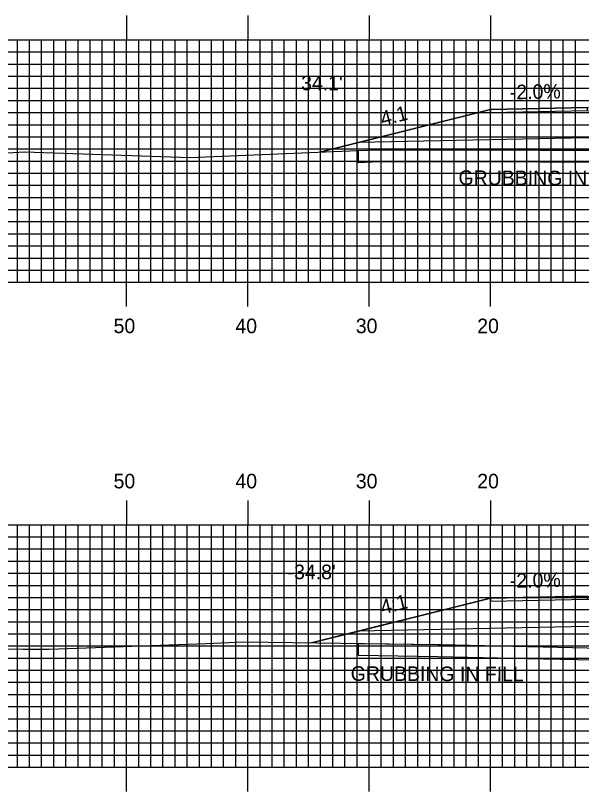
# Model space of a CAD drawing. Extents: x 1814522 to 1814865, y 442591 to 442811.
# Drawn here: x 1814628.4 to 1814675, y 442686.7 to 442750.7 of the extents above; entities that cross this region are included whole.
import ezdxf

# ---------------------------------------------------------------- set-up
doc = ezdxf.new("R2010")
doc.units = 0
for name, color, linetype in [('ANNOTATION', 7, 'Continuous'), ('D_Roadway_Centerline', 7, 'Continuous'), ('D_Roadway_Edge_Shoulder', 7, 'Continuous'), ('D_Roadway_SlopeLines', 7, 'Continuous'), ('D_Roadway_SubGrade', 7, 'Continuous'), ('D_Text_Standard', 7, 'Continuous'), ('GRUBBING IN FILL', 7, 'Continuous'), ('H_V ANNOTATION', 7, 'Continuous'), ('MAJOR', 7, 'Continuous'), ('MINOR', 7, 'Continuous'), ('S_Roadway_Centerline', 7, 'Continuous')]:
    doc.layers.add(name, color=color, linetype=linetype)

msp = doc.modelspace()

# ---------------------------------------------------------------- linework, layer by layer
at = {"layer": 'D_Roadway_Centerline'}
for points in [[(1814653.448, 442739.4), (1814656.638, 442740.197), (1814667.508, 442742.915), (1814675.508, 442743.075), (1814687.508, 442742.499), (1814699.508, 442741.923), (1814707.508, 442741.539), (1814719.884, 442738.445), (1814723.884, 442737.445), (1814725.374, 442738.19), (1814726.624, 442738.721), (1814727.874, 442739.063), (1814729.124, 442739.217), (1814730.374, 442739.183)], [(1814652.747, 442698.927), (1814656.638, 442699.899), (1814667.508, 442702.617), (1814675.508, 442702.777), (1814687.508, 442702.201), (1814699.508, 442701.625), (1814707.508, 442701.241), (1814719.884, 442698.147), (1814723.884, 442697.147), (1814725.557, 442697.984), (1814726.807, 442698.531), (1814728.057, 442698.923), (1814729.307, 442699.16), (1814730.557, 442699.241)]]:
    msp.add_lwpolyline(points, dxfattribs=at)
at = {"layer": 'D_Roadway_Edge_Shoulder'}
for points in [[(1814675.508, 442743.075), (1814667.508, 442742.915), (1814667.508, 442742.665), (1814675.508, 442742.825)], [(1814675.508, 442702.777), (1814667.508, 442702.617), (1814667.508, 442702.367), (1814675.508, 442702.527)]]:
    msp.add_lwpolyline(points, close=True, dxfattribs=at)
at = {"layer": 'D_Roadway_SlopeLines'}
for points in [[(1814667.508, 442742.915), (1814653.448, 442739.4)], [(1814667.508, 442702.617), (1814652.747, 442698.927)]]:
    msp.add_lwpolyline(points, dxfattribs=at)
at = {"layer": 'D_Roadway_SubGrade'}
for points in [[(1814675.508, 442740.575), (1814656.638, 442740.197), (1814667.508, 442742.915), (1814667.508, 442742.665), (1814675.508, 442742.825), (1814687.508, 442742.249), (1814699.508, 442741.673), (1814707.508, 442741.289), (1814707.508, 442741.539), (1814719.884, 442738.445), (1814699.508, 442739.423), (1814687.508, 442739.999)], [(1814675.508, 442700.277), (1814656.638, 442699.899), (1814667.508, 442702.617), (1814667.508, 442702.367), (1814675.508, 442702.527), (1814687.508, 442701.951), (1814699.508, 442701.375), (1814707.508, 442700.991), (1814707.508, 442701.241), (1814719.884, 442698.147), (1814699.508, 442699.125), (1814687.508, 442699.701)]]:
    msp.add_lwpolyline(points, close=True, dxfattribs=at)
at = {"layer": 'GRUBBING IN FILL'}
for points in [[(1814656.638, 442739.528), (1814658.134, 442739.6), (1814671.642, 442739.571), (1814684.967, 442739.552), (1814687.508, 442739.596), (1814687.508, 442738.596), (1814684.975, 442738.552), (1814671.633, 442738.571), (1814658.291, 442738.591), (1814656.638, 442738.527)], [(1814656.638, 442739.528), (1814658.134, 442739.6), (1814671.642, 442739.571), (1814684.967, 442739.552), (1814687.508, 442739.596), (1814687.508, 442738.596), (1814684.975, 442738.552), (1814671.633, 442738.571), (1814658.291, 442738.591), (1814656.638, 442738.527)], [(1814656.638, 442698.871), (1814663.185, 442698.778), (1814671.839, 442698.589), (1814680.303, 442698.403), (1814684.531, 442698.645), (1814687.508, 442698.782), (1814687.508, 442697.781), (1814684.582, 442697.646), (1814682.451, 442697.525), (1814680.32, 442697.403), (1814671.838, 442697.589), (1814663.17, 442697.778), (1814656.638, 442697.871)], [(1814656.638, 442698.871), (1814663.185, 442698.778), (1814671.839, 442698.589), (1814680.303, 442698.403), (1814684.531, 442698.645), (1814687.508, 442698.782), (1814687.508, 442697.781), (1814684.582, 442697.646), (1814682.451, 442697.525), (1814680.32, 442697.403), (1814671.838, 442697.589), (1814663.17, 442697.778), (1814656.638, 442697.871)]]:
    msp.add_lwpolyline(points, close=True, dxfattribs=at)
at = {"layer": 'MAJOR'}
for p, q in [((1814637.508, 442750.669), (1814637.508, 442748.665)), ((1814647.508, 442750.669), (1814647.508, 442748.665)), ((1814657.508, 442750.669), (1814657.508, 442748.665)), ((1814667.508, 442750.669), (1814667.508, 442748.665)), ((1814547.508, 442748.665), (1814827.508, 442748.665)), ((1814547.508, 442748.665), (1814827.508, 442748.665)), ((1814637.508, 442728.665), (1814637.508, 442748.665)), ((1814647.508, 442728.665), (1814647.508, 442748.665)), ((1814657.508, 442728.665), (1814657.508, 442748.665)), ((1814667.508, 442728.665), (1814667.508, 442748.665)), ((1814547.508, 442743.665), (1814827.508, 442743.665)), ((1814547.508, 442738.665), (1814827.508, 442738.665)), ((1814547.508, 442733.665), (1814827.508, 442733.665)), ((1814547.508, 442728.665), (1814827.508, 442728.665)), ((1814547.508, 442728.665), (1814827.508, 442728.665)), ((1814637.508, 442726.661), (1814637.508, 442728.665)), ((1814647.508, 442726.661), (1814647.508, 442728.665)), ((1814657.508, 442726.661), (1814657.508, 442728.665)), ((1814667.508, 442726.661), (1814667.508, 442728.665)), ((1814637.508, 442710.669), (1814637.508, 442708.665)), ((1814647.508, 442710.669), (1814647.508, 442708.665)), ((1814657.508, 442710.669), (1814657.508, 442708.665)), ((1814667.508, 442710.669), (1814667.508, 442708.665)), ((1814547.508, 442708.665), (1814827.508, 442708.665)), ((1814547.508, 442708.665), (1814827.508, 442708.665)), ((1814637.508, 442688.665), (1814637.508, 442708.665)), ((1814647.508, 442688.665), (1814647.508, 442708.665)), ((1814657.508, 442688.665), (1814657.508, 442708.665)), ((1814667.508, 442688.665), (1814667.508, 442708.665)), ((1814547.508, 442703.665), (1814827.508, 442703.665)), ((1814547.508, 442698.665), (1814827.508, 442698.665)), ((1814547.508, 442693.665), (1814827.508, 442693.665)), ((1814547.508, 442688.665), (1814827.508, 442688.665)), ((1814547.508, 442688.665), (1814827.508, 442688.665)), ((1814637.508, 442686.661), (1814637.508, 442688.665)), ((1814647.508, 442686.661), (1814647.508, 442688.665)), ((1814657.508, 442686.661), (1814657.508, 442688.665)), ((1814667.508, 442686.661), (1814667.508, 442688.665))]:
    msp.add_line(p, q, dxfattribs=at)
at = {"layer": 'MINOR'}
for p, q in [((1814628.508, 442728.665), (1814628.508, 442748.665)), ((1814629.508, 442728.665), (1814629.508, 442748.665)), ((1814630.508, 442728.665), (1814630.508, 442748.665)), ((1814631.508, 442728.665), (1814631.508, 442748.665)), ((1814632.508, 442728.665), (1814632.508, 442748.665)), ((1814633.508, 442728.665), (1814633.508, 442748.665)), ((1814634.508, 442728.665), (1814634.508, 442748.665)), ((1814635.508, 442728.665), (1814635.508, 442748.665)), ((1814636.508, 442728.665), (1814636.508, 442748.665)), ((1814638.508, 442728.665), (1814638.508, 442748.665)), ((1814639.508, 442728.665), (1814639.508, 442748.665)), ((1814640.508, 442728.665), (1814640.508, 442748.665)), ((1814641.508, 442728.665), (1814641.508, 442748.665)), ((1814642.508, 442728.665), (1814642.508, 442748.665)), ((1814643.508, 442728.665), (1814643.508, 442748.665)), ((1814644.508, 442728.665), (1814644.508, 442748.665)), ((1814645.508, 442728.665), (1814645.508, 442748.665)), ((1814646.508, 442728.665), (1814646.508, 442748.665)), ((1814648.508, 442728.665), (1814648.508, 442748.665)), ((1814649.508, 442728.665), (1814649.508, 442748.665)), ((1814650.508, 442728.665), (1814650.508, 442748.665)), ((1814651.508, 442728.665), (1814651.508, 442748.665)), ((1814652.508, 442728.665), (1814652.508, 442748.665)), ((1814653.508, 442728.665), (1814653.508, 442748.665)), ((1814654.508, 442728.665), (1814654.508, 442748.665)), ((1814655.508, 442728.665), (1814655.508, 442748.665)), ((1814656.508, 442728.665), (1814656.508, 442748.665)), ((1814658.508, 442728.665), (1814658.508, 442748.665)), ((1814659.508, 442728.665), (1814659.508, 442748.665)), ((1814660.508, 442728.665), (1814660.508, 442748.665)), ((1814661.508, 442728.665), (1814661.508, 442748.665)), ((1814662.508, 442728.665), (1814662.508, 442748.665)), ((1814663.508, 442728.665), (1814663.508, 442748.665)), ((1814664.508, 442728.665), (1814664.508, 442748.665)), ((1814665.508, 442728.665), (1814665.508, 442748.665)), ((1814666.508, 442728.665), (1814666.508, 442748.665)), ((1814668.508, 442728.665), (1814668.508, 442748.665)), ((1814669.508, 442728.665), (1814669.508, 442748.665)), ((1814670.508, 442728.665), (1814670.508, 442748.665)), ((1814671.508, 442728.665), (1814671.508, 442748.665)), ((1814672.508, 442728.665), (1814672.508, 442748.665)), ((1814673.508, 442728.665), (1814673.508, 442748.665)), ((1814674.508, 442728.665), (1814674.508, 442748.665)), ((1814547.508, 442747.665), (1814827.508, 442747.665)), ((1814547.508, 442746.665), (1814827.508, 442746.665)), ((1814547.508, 442745.665), (1814827.508, 442745.665)), ((1814547.508, 442744.665), (1814827.508, 442744.665)), ((1814547.508, 442742.665), (1814827.508, 442742.665)), ((1814547.508, 442741.665), (1814827.508, 442741.665)), ((1814547.508, 442740.665), (1814827.508, 442740.665)), ((1814547.508, 442739.665), (1814827.508, 442739.665)), ((1814547.508, 442737.665), (1814827.508, 442737.665)), ((1814547.508, 442736.665), (1814827.508, 442736.665)), ((1814547.508, 442735.665), (1814827.508, 442735.665)), ((1814547.508, 442734.665), (1814827.508, 442734.665)), ((1814547.508, 442732.665), (1814827.508, 442732.665)), ((1814547.508, 442731.665), (1814827.508, 442731.665)), ((1814547.508, 442730.665), (1814827.508, 442730.665)), ((1814547.508, 442729.665), (1814827.508, 442729.665)), ((1814628.508, 442688.665), (1814628.508, 442708.665)), ((1814629.508, 442688.665), (1814629.508, 442708.665)), ((1814630.508, 442688.665), (1814630.508, 442708.665)), ((1814631.508, 442688.665), (1814631.508, 442708.665)), ((1814632.508, 442688.665), (1814632.508, 442708.665)), ((1814633.508, 442688.665), (1814633.508, 442708.665)), ((1814634.508, 442688.665), (1814634.508, 442708.665)), ((1814635.508, 442688.665), (1814635.508, 442708.665)), ((1814636.508, 442688.665), (1814636.508, 442708.665)), ((1814638.508, 442688.665), (1814638.508, 442708.665)), ((1814639.508, 442688.665), (1814639.508, 442708.665)), ((1814640.508, 442688.665), (1814640.508, 442708.665)), ((1814641.508, 442688.665), (1814641.508, 442708.665)), ((1814642.508, 442688.665), (1814642.508, 442708.665)), ((1814643.508, 442688.665), (1814643.508, 442708.665)), ((1814644.508, 442688.665), (1814644.508, 442708.665)), ((1814645.508, 442688.665), (1814645.508, 442708.665)), ((1814646.508, 442688.665), (1814646.508, 442708.665)), ((1814648.508, 442688.665), (1814648.508, 442708.665)), ((1814649.508, 442688.665), (1814649.508, 442708.665)), ((1814650.508, 442688.665), (1814650.508, 442708.665)), ((1814651.508, 442688.665), (1814651.508, 442708.665)), ((1814652.508, 442688.665), (1814652.508, 442708.665)), ((1814653.508, 442688.665), (1814653.508, 442708.665)), ((1814654.508, 442688.665), (1814654.508, 442708.665)), ((1814655.508, 442688.665), (1814655.508, 442708.665)), ((1814656.508, 442688.665), (1814656.508, 442708.665)), ((1814658.508, 442688.665), (1814658.508, 442708.665)), ((1814659.508, 442688.665), (1814659.508, 442708.665)), ((1814660.508, 442688.665), (1814660.508, 442708.665)), ((1814661.508, 442688.665), (1814661.508, 442708.665)), ((1814662.508, 442688.665), (1814662.508, 442708.665)), ((1814663.508, 442688.665), (1814663.508, 442708.665)), ((1814664.508, 442688.665), (1814664.508, 442708.665)), ((1814665.508, 442688.665), (1814665.508, 442708.665)), ((1814666.508, 442688.665), (1814666.508, 442708.665)), ((1814668.508, 442688.665), (1814668.508, 442708.665)), ((1814669.508, 442688.665), (1814669.508, 442708.665)), ((1814670.508, 442688.665), (1814670.508, 442708.665)), ((1814671.508, 442688.665), (1814671.508, 442708.665)), ((1814672.508, 442688.665), (1814672.508, 442708.665)), ((1814673.508, 442688.665), (1814673.508, 442708.665)), ((1814674.508, 442688.665), (1814674.508, 442708.665)), ((1814547.508, 442707.665), (1814827.508, 442707.665)), ((1814547.508, 442706.665), (1814827.508, 442706.665)), ((1814547.508, 442705.665), (1814827.508, 442705.665)), ((1814547.508, 442704.665), (1814827.508, 442704.665)), ((1814547.508, 442702.665), (1814827.508, 442702.665)), ((1814547.508, 442701.665), (1814827.508, 442701.665)), ((1814547.508, 442700.665), (1814827.508, 442700.665)), ((1814547.508, 442699.665), (1814827.508, 442699.665)), ((1814547.508, 442697.665), (1814827.508, 442697.665)), ((1814547.508, 442696.665), (1814827.508, 442696.665)), ((1814547.508, 442695.665), (1814827.508, 442695.665)), ((1814547.508, 442694.665), (1814827.508, 442694.665)), ((1814547.508, 442692.665), (1814827.508, 442692.665)), ((1814547.508, 442691.665), (1814827.508, 442691.665)), ((1814547.508, 442690.665), (1814827.508, 442690.665)), ((1814547.508, 442689.665), (1814827.508, 442689.665))]:
    msp.add_line(p, q, dxfattribs=at)
at = {"layer": 'S_Roadway_Centerline'}
for points in [[(1814547.508, 442736.831), (1814557.042, 442737.108), (1814559.077, 442737.2), (1814562.028, 442737.26), (1814576.198, 442737.904), (1814586.683, 442738.796), (1814593.172, 442738.958), (1814599.985, 442738.663), (1814608.419, 442738.425), (1814620.662, 442739.175), (1814625.399, 442739.21), (1814629.103, 442739.434), (1814642.752, 442738.971), (1814656.576, 442739.525), (1814658.134, 442739.6), (1814658.317, 442739.591), (1814684.967, 442739.552), (1814692.006, 442739.674), (1814696.955, 442739.753), (1814709.165, 442739.797), (1814718.813, 442739.807), (1814725.616, 442739.672), (1814732.236, 442738.992), (1814742.086, 442738.733)], [(1814547.508, 442697.837), (1814549.775, 442697.725), (1814555.438, 442697.738), (1814566.513, 442698.088), (1814573.411, 442698.426), (1814590, 442699.042), (1814598.779, 442699.54), (1814610.82, 442698.849), (1814614.579, 442698.703), (1814628.995, 442698.398), (1814631.137, 442698.395), (1814644.071, 442698.878), (1814647.187, 442699.006), (1814663.185, 442698.778), (1814663.374, 442698.775), (1814680.303, 442698.403), (1814684.531, 442698.645), (1814698.307, 442699.279), (1814709.411, 442699.333), (1814714.7, 442698.855), (1814721.941, 442699.198), (1814730.176, 442699.246), (1814739.585, 442699.133)]]:
    msp.add_lwpolyline(points, dxfattribs=at)

# ---------------------------------------------------------------- texts
at = {"layer": 'ANNOTATION'}
for s, rotation, p in [('-2.0%', 1.14576, (1814669.114, 442743.747)), ('4:1', 14.03624, (1814658.608, 442741.551)), ('-2.0%', 1.14576, (1814669.114, 442703.449)), ('4:1', 14.03624, (1814658.608, 442701.254))]:
    msp.add_text(s, height=1.2, rotation=rotation, dxfattribs=at).set_placement(p)
at = {"layer": 'D_Text_Standard'}
for s, p in [("34.1'", (1814651.899, 442744.504)), ("-34.8'", (1814650.782, 442704.173))]:
    msp.add_text(s, height=1.2, dxfattribs=at).set_placement(p)
at = {"layer": 'GRUBBING IN FILL'}
for p in [(1814664.868, 442736.695), (1814655.983, 442695.792)]:
    msp.add_text('GRUBBING IN FILL', height=1.2, rotation=359.80532, dxfattribs=at).set_placement(p)
at = {"layer": 'H_V ANNOTATION'}
for s, p in [('50', (1814636.437, 442724.465)), ('40', (1814646.48, 442724.465)), ('30', (1814656.405, 442724.465)), ('20', (1814666.415, 442724.465)), ('50', (1814636.437, 442711.665)), ('40', (1814646.48, 442711.665)), ('30', (1814656.405, 442711.665)), ('20', (1814666.415, 442711.665))]:
    msp.add_text(s, height=1.2, dxfattribs=at).set_placement(p)

doc.saveas('drawing.dxf')
